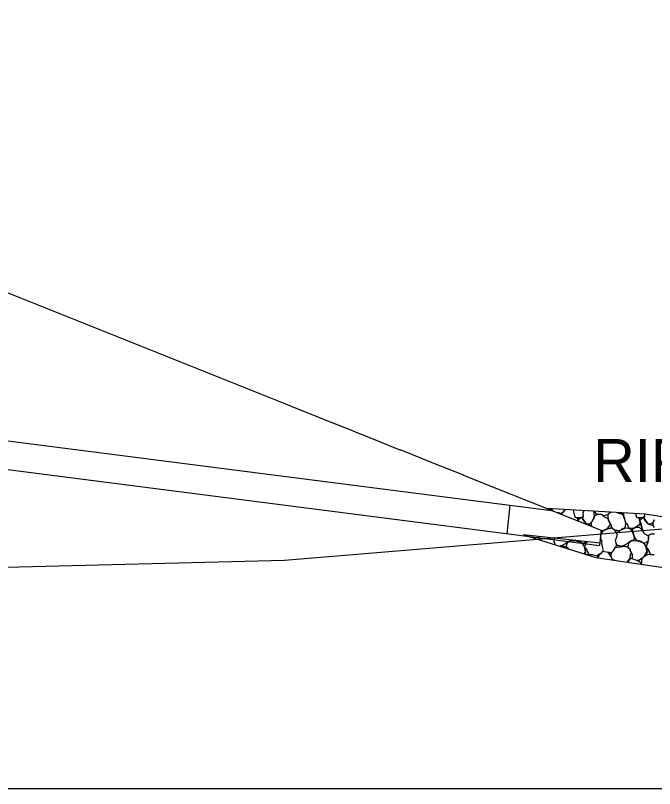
# Model space of a CAD drawing. Extents: x -26 to 630, y -39 to 9098.
# Drawn here: x 383.5 to 428, y 4000 to 4053.8 of the extents above; entities that cross this region are included whole.
import ezdxf

# ---------------------------------------------------------------- set-up
doc = ezdxf.new("R2010")
doc.units = 0
for name, color, linetype in [('1', 7, 'Continuous'), ('Default', 7, 'Continuous'), ('DTM_X_GROUND', 7, 'Continuous'), ('XS_CELL', 7, 'Continuous'), ('XS_P_DRAINAGE', 7, 'Continuous'), ('XS_P_GROUND', 7, 'Continuous')]:
    doc.layers.add(name, color=color, linetype=linetype)

msp = doc.modelspace()

# ---------------------------------------------------------------- linework, layer by layer
at = {"layer": '1'}
for p, q in [((420.752, 4019.38), (420.787, 4019.467)), ((420.787, 4019.467), (420.752, 4019.38)), ((424.892, 4019.213), (424.96, 4019.229)), ((418.87, 4017.652), (418.87, 4017.652)), ((419.049, 4017.633), (418.996, 4017.613))]:
    msp.add_line(p, q, dxfattribs=at)
for points in [[(420.936, 4019.306), (420.892, 4019.343), (420.866, 4019.463)], [(421.774, 4019.411), (421.572, 4019.153), (421.482, 4019.143), (421.213, 4019.194)], [(421.562, 4019.054), (421.542, 4019.163), (421.766, 4019.411)], [(422.334, 4019.379), (422.342, 4019.273), (422.442, 4018.883), (422.622, 4018.833), (422.672, 4018.683), (422.678, 4018.604)], [(422.337, 4019.379), (422.342, 4019.263), (422.452, 4018.893), (422.602, 4018.823), (422.682, 4018.673), (422.703, 4018.593)], [(422.693, 4018.597), (422.672, 4018.673), (422.792, 4018.793), (422.922, 4018.853), (422.592, 4018.833), (422.942, 4018.853), (423.022, 4018.713), (423.242, 4018.423), (423.602, 4018.303), (423.651, 4018.211)], [(423.648, 4018.212), (423.602, 4018.293), (423.602, 4018.473), (423.692, 4018.693), (423.582, 4018.473), (423.412, 4018.393), (423.262, 4018.403), (423.002, 4018.723), (423.012, 4018.923), (422.922, 4018.873), (423.042, 4018.923), (423.032, 4019.173), (423.092, 4019.335)], [(424.228, 4017.609), (424.312, 4017.753), (424.382, 4017.903), (424.382, 4017.943), (424.722, 4018.083), (424.922, 4018.373), (424.782, 4018.663), (424.752, 4018.763), (424.492, 4018.893), (424.412, 4018.973), (424.322, 4019.063), (424.112, 4019.093), (424.012, 4019.063), (423.842, 4018.983), (423.722, 4018.693), (423.822, 4018.973), (423.762, 4019.293), (423.758, 4019.297)], [(423.81, 4019.294), (423.902, 4019.133), (424.022, 4019.073), (424.122, 4019.093), (424.312, 4019.073), (424.432, 4018.983), (424.772, 4019.053), (424.919, 4019.231)], [(424.907, 4019.232), (424.862, 4019.183), (424.742, 4019.053), (424.732, 4018.863), (424.772, 4018.743), (424.952, 4018.353), (424.992, 4018.143), (424.732, 4018.073), (425.042, 4018.143), (425.232, 4017.963), (425.372, 4017.723), (425.362, 4017.523), (425.242, 4017.253), (425.322, 4017.033), (425.312, 4016.863), (425.172, 4016.673), (425.152, 4016.613), (425.242, 4016.763), (425.612, 4016.813), (425.592, 4016.863), (425.332, 4016.963), (425.622, 4016.843), (425.752, 4016.843), (425.922, 4016.853), (426.132, 4016.783), (426.272, 4016.683), (426.282, 4016.613), (426.272, 4016.673), (426.142, 4016.793), (426.152, 4016.893), (426.222, 4017.113), (425.922, 4016.923), (425.622, 4016.843)], [(425.356, 4019.206), (425.732, 4019.083), (425.842, 4018.913), (425.962, 4018.443), (425.932, 4018.143), (425.702, 4018.033), (425.632, 4017.973), (425.362, 4017.773), (425.232, 4017.963), (425.362, 4017.963), (425.462, 4017.923), (425.612, 4017.973), (425.962, 4018.133), (426.172, 4018.103), (426.282, 4018.063), (426.472, 4017.833), (426.572, 4017.543), (426.542, 4017.283), (426.372, 4017.223), (426.232, 4017.123), (426.352, 4017.223), (426.592, 4017.263), (426.812, 4017.233), (427.042, 4017.163), (427.212, 4017.093), (427.402, 4016.783), (427.432, 4016.603), (427.402, 4016.793), (427.542, 4016.623), (427.402, 4016.803), (427.552, 4017.133), (427.592, 4017.633), (427.772, 4017.713), (427.902, 4017.693), (427.982, 4017.733), (427.932, 4017.693), (427.782, 4017.723), (427.612, 4017.633), (427.532, 4017.603), (427.562, 4017.393), (427.522, 4017.183), (427.412, 4017.083), (427.222, 4017.053), (427.052, 4017.193), (426.762, 4017.253), (426.572, 4017.523), (426.462, 4017.863), (426.462, 4018.043), (426.702, 4018.183), (426.912, 4018.183), (427.142, 4017.943), (427.262, 4017.753), (427.512, 4017.603)], [(425.87, 4019.177), (425.852, 4019.153), (425.762, 4019.143), (425.464, 4019.2)], [(426.658, 4019.131), (426.722, 4018.883), (426.902, 4018.833), (426.952, 4018.683), (426.972, 4018.433), (426.862, 4018.303), (426.692, 4018.183), (426.552, 4018.103), (426.232, 4018.083), (426.072, 4018.403), (425.992, 4018.453), (425.922, 4018.753), (425.842, 4018.883), (425.842, 4019.053), (425.822, 4019.163), (425.835, 4019.179)], [(426.661, 4019.131), (426.732, 4018.893), (426.882, 4018.823), (426.962, 4018.673), (427.162, 4017.933), (426.952, 4018.673), (427.072, 4018.793), (427.202, 4018.853), (426.872, 4018.833), (427.222, 4018.853), (427.302, 4018.713), (427.522, 4018.423), (427.882, 4018.303), (427.962, 4018.153), (427.882, 4018.293), (427.882, 4018.473), (427.972, 4018.693), (427.862, 4018.473), (427.692, 4018.393), (427.542, 4018.403), (427.282, 4018.723), (427.292, 4018.923), (427.202, 4018.873), (427.322, 4018.923), (427.315, 4019.094)], [(424.256, 4017.879), (424.382, 4017.933), (424.732, 4018.063), (424.392, 4017.903), (424.312, 4017.763), (424.228, 4017.612)], [(419.029, 4017.602), (419.032, 4017.633), (419.033, 4017.634)], [(420.013, 4017.293), (419.942, 4017.513), (419.903, 4017.538)], [(421.032, 4017.412), (420.962, 4017.253), (421.042, 4017.033), (421.038, 4016.971)], [(422.243, 4017.277), (422.092, 4017.223), (421.952, 4017.123), (422.072, 4017.223), (422.312, 4017.263), (422.532, 4017.233), (422.762, 4017.163), (422.932, 4017.093), (423.122, 4016.783), (423.152, 4016.603), (423.122, 4016.793), (423.262, 4016.623), (423.122, 4016.803), (423.272, 4017.133), (423.274, 4017.162)], [(423.224, 4017.168), (423.132, 4017.083), (422.942, 4017.053), (422.772, 4017.193), (422.512, 4017.247)], [(424.412, 4016.623), (424.312, 4017.063), (424.342, 4017.143), (424.222, 4017.513), (424.218, 4017.516)], [(421.992, 4016.672), (421.992, 4016.673), (421.862, 4016.793), (421.872, 4016.893), (421.942, 4017.113), (421.642, 4016.923), (421.398, 4016.858)], [(421.445, 4016.843), (421.472, 4016.843), (421.642, 4016.853), (421.852, 4016.783), (421.992, 4016.683), (421.993, 4016.671)], [(423.101, 4016.323), (423.182, 4016.453), (423.162, 4016.583), (423.192, 4016.443), (423.113, 4016.32)], [(423.692, 4016.253), (423.432, 4016.263), (423.282, 4016.603), (423.422, 4016.263), (423.252, 4016.283), (423.242, 4016.279)], [(423.722, 4016.253), (423.982, 4016.203), (424.052, 4016.053), (424.232, 4016.343), (423.972, 4016.203), (424.302, 4016.383), (424.392, 4016.493), (424.402, 4016.583), (424.382, 4016.513), (424.732, 4016.453), (424.922, 4016.163), (424.992, 4016.403), (424.732, 4016.443), (424.992, 4016.393), (425.172, 4016.603), (424.972, 4016.403), (424.942, 4016.163), (425.022, 4015.973), (425.202, 4015.883), (425.205, 4015.877)], [(427.039, 4015.606), (427.022, 4015.703), (426.782, 4015.863), (426.942, 4015.903), (427.042, 4015.983), (427.092, 4015.973), (427.022, 4015.973), (426.942, 4015.883), (426.762, 4015.863), (426.352, 4016.003), (426.282, 4016.033), (426.322, 4016.263), (426.382, 4016.363), (426.302, 4016.573), (426.432, 4016.273), (426.442, 4015.983)], [(427.972, 4016.253), (427.712, 4016.263), (427.562, 4016.603), (427.702, 4016.263), (427.532, 4016.283), (427.282, 4016.163), (427.462, 4016.453), (427.442, 4016.583), (427.472, 4016.443), (427.282, 4016.143), (427.092, 4016.003), (427.063, 4015.602)], [(424.049, 4016.048), (424.042, 4016.063), (424.048, 4016.048)], [(426.103, 4015.744), (426.342, 4016.013), (426.262, 4016.033), (426.069, 4015.75)]]:
    msp.add_lwpolyline(points, dxfattribs=at)
at = {"layer": 'DTM_X_GROUND'}
msp.add_lwpolyline([(381.28, 4015.368), (383.785, 4015.43), (402.257, 4015.885), (511.505, 4024.957)], dxfattribs=at)
at = {"layer": 'XS_CELL'}
msp.add_line((100, 4000), (450, 4000), dxfattribs=at)
at = {"layer": 'XS_P_DRAINAGE'}
for p, q in [((311.394, 4033.388), (420.811, 4019.345)), ((311.173, 4031.4), (424.154, 4016.9)), ((417.931, 4019.715), (417.724, 4017.725)), ((424.265, 4017.964), (424.154, 4016.9))]:
    msp.add_line(p, q, dxfattribs=at)
msp.add_lwpolyline([(418.869, 4017.653), (423.912, 4016.069), (458.517, 4010.949), (460.265, 4011.52), (441.189, 4016.911), (427.324, 4019.093), (420.495, 4019.484), (424.265, 4017.964), (424.171, 4017.063)], close=True, dxfattribs=at)
at = {"layer": 'XS_P_GROUND'}
msp.add_lwpolyline([(424.184, 4017.996), (418.89, 4020.113), (417.979, 4020.478), (417.897, 4020.511), (414.726, 4021.779), (414.644, 4021.812), (412.529, 4022.658), (412.474, 4022.68), (410.357, 4023.527), (410.303, 4023.548), (408.184, 4024.396), (408.13, 4024.418), (407.07, 4024.842), (407.042, 4024.852), (404.922, 4025.701), (404.867, 4025.723), (402.746, 4026.571), (402.691, 4026.593), (334.728, 4053.778)], dxfattribs=at)

# ---------------------------------------------------------------- texts
at = {"layer": 'Default'}
msp.add_text('X', height=0.12, dxfattribs=at).set_placement((420.864, 4019.248))
at = {"layer": 'XS_P_DRAINAGE'}
msp.add_text('RIPRAP BASIN', height=3, dxfattribs=at).set_placement((423.719, 4021.313))

doc.saveas('drawing.dxf')
